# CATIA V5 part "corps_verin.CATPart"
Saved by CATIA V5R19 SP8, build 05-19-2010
Part number: corps vérin
Bounding box of the stored display mesh (mm): x -474.945 to 1485, y -240 to 240, z -240 to 240
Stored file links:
  C:\Users\ThinkMotion\Desktop\EU_thinkMotion\iao\IAO_MMS_Groupe3\gdespas\projet_Thinkmotion_GDESPAS\projet Thinkmotion GDESPAS\Assemblage gdespas\corps_verin.CATPart
  C:\Users\ThinkMotion\Desktop\EU_thinkMotion\iao\IAO_MMS_Groupe3\gdespas\projet_Thinkmotion_GDESPAS\projet Thinkmotion GDESPAS\Assemblage gdespas\Assemblage IAO.CATProduct
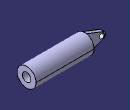
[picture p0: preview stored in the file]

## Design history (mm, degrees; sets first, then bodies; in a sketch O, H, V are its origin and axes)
External parameters (linked from other documents)
  External.diam_axe = 0.126
Body1 (main body)
  Sketch1 on yz-plane, origin (0, 0, 0), H (0, 1, 0), V (0, 0, 1)
    circle A1 centre (0, 0) radius 240
    radius A1 = 240
  Pad1: profile Sketch1, direction (1, 0, 0), length 1485
  Sketch2 on end face of Pad1, origin (1485, 0, 0), H (0, 1, 0), V (0, 0, 1)
    point P1 (0, 0)
  Hole1: placed by Sketch2, at (1485, 0, 0) direction (-1, 0, 0), diameter 220, depth 1470
  Sketch3 on zx-plane, origin (0, 0, 0), H (-1, 0, 0), V (0, 0, 1)
    circle A1 centre (385, 0) radius 63
    point P1 (385, 0)
    reference projected line E1 (0, -240) -> (0, 240) from edge [start face of Pad1 | face of Pad1 from Sketch1.A1]
    line L1 (0, -240) -> (441.78, -69.8286)
    point P2 (0, -240)
    line L2 (0, 240) -> (446.0113, 66.1635)
    point P4 (0, 240)
    point P5 (446.0113, 66.1635)
    arc A2 centre (385, 0) radius 90 from (441.78, -69.8286) to (446.0113, 66.1635) ccw
    point P6 (446.0113, 66.1635)
    line L3 (0, -240) -> (0, 240)
    reference intersected line E2 through (0, 0) direction (-1, 0) from xy-plane
    distance P1 E1 = 385
    distance P4 E2 = 240
    radius A1 = 63 {= External.diam_axe /2}
    radius A2 = 90
    length L1 = 473.4215
    length L2 = 478.6912
    distance P2 O = 240
    coincidence: P1 H, P2 V, P4 V, P6 L2, P5 P6
    vertical: L3 V
  Pad2: profile Sketch3, direction (0, 1, 0), length 50, opposite side length 50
